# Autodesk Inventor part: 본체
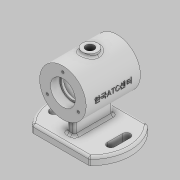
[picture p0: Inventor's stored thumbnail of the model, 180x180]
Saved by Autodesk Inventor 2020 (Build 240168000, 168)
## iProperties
Created: 2021-09
Part Number: 본체
Material: 일반
Document SubType Name: Modeling
Designer: Administrator
Density: 1 g/cm^3
Appearance: 기본값
Mass: 173.412 g
Surface Area: 488.146 cm^2
Volume: 173.412 cm^3
Author: Administrator
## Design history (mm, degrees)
sketch "스케치1"
  geometry: C1 r 30 at (0, 62); 1 further point
  constraints: 1 centre point
  dimensions: "d0" = 60 diameter of C1; "d1" = 62 distance of point (0, 0) C1.centre
extrude "돌출1" new body sketch "스케치1" stored distance "d2" = 70; taper "d3" = 0 deg
sketch "스케치2"
  geometry: C1 r 52.5 at (0, 0); 1 further point
  constraints: 1 centre point, 1 coincident
  dimensions: "d4" = 105 diameter of C1
extrude "돌출2" join sketch "스케치2" distance "d5" = 10; taper "d6" = 0 deg
sketch "스케치4"
  geometry: L1 (-122.101, -120.622)-(97.742, -120.622); L2 (97.742, -120.622)-(97.742, -37.5); L3 (97.742, -37.5)-(-122.101, -37.5); L4 (-122.101, -37.5)-(-122.101, -120.622); L5 (-52.5, 0)-(52.5, 0); A1 r 52.5 centre (0, 0) between (-52.5, 0) and (52.5, 0) reference; 2 further points
  constraints: 10 end point, 2 horizontal, 2 parallel, 2 point on circle, 1 coincident, 1 midpoint, 1 perpendicular
  dimensions: "d8" = 37.5 distance between parallel lines of L3 L5
extrude "돌출3" cut sketch "스케치4" extent not by distance; stored distance "d9" = 0; taper "d10" = 0 deg
sketch "스케치3"
  geometry: L1 (35.4, 25)-(4, 25); L2 (4, 25)-(4, -25); L3 (4, -25)-(35.4, -25); L4 (35.4, -25)-(35.4, 25); L5 (0, 0)-(92, 0); L6 (92, -35)-(92, 35) reference
  constraints: 10 end point, 2 parallel, 1 horizontal, 1 midpoint, 1 perpendicular, 1 other
  dimensions: "d7" = 50 distance of L3.end L1.start
extrude "돌출4" join sketch "스케치3" stored distance "d11" = 10; taper "d12" = 0 deg
sketch "스케치5"
  geometry: L1 (92, 35)-(32, 35) reference; L2 (62, 35)-(62, -35); L3 (32, -35)-(92, -35) reference; L4 (62, 35)-(78, 35); L5 (78, 35)-(78, 23); L6 (78, 23)-(76, 23); L7 (76, 23)-(76, 20); L8 (76, 20)-(87, 20); L9 (87, 20)-(87, -20); L10 (87, -20)-(76, -20); L11 (76, -20)-(76, -23); L12 (76, -23)-(78, -23); L13 (78, -23)-(78, -35); L14 (78, -35)-(62, -35); 1 further point
  constraints: 24 end point, 7 perpendicular, 2 midpoint, 2 point on line, 1 collinear, 1 horizontal, 1 vertical
  dimensions: "d13" = 28 diameter of L7 L2; "d14" = 28 diameter of L11 L2 (= d13); "d15" = 32 diameter of L5 L2; "d16" = 32 diameter of L13 L2 (= d15); "d17" = 50 diameter of L9 L2; "d18" = 12 distance of L4.end L5.end; "d19" = 12 distance of L12.end L13.end (= d18); "d20" = 40 distance of L8.end L9.end; "d21" = 3 distance of L6.end L7.end
revolve "회전1" sketch "스케치5" stored, may be unused: angle "d22" = 90 deg
sketch "스케치6"
  geometry: C1 r 30 at (0, 0) reference; 2 further points
  constraints: 1 vertical alignment
  dimensions: "d23" = 23 distance of C1.centre point (0, 23)
hole "구멍1" sketch "스케치6" at (0, 23) diameter "d24" = 3.242; stored, may be unused: countersink angle "d28" = 90 deg, drill point angle "d30" = 118 deg; dims "d25" = 8, "d26" = 4, "d27" = 2, "d29" = 10
node "작업 평면2"
sketch "스케치7"
  geometry: C1 r 10 at (0, 0); 1 further point
  constraints: 1 centre point, 1 coincident
  dimensions: "d36" = 20 diameter of C1
extrude "돌출5" join sketch "스케치7" stored distance "d37" = 10; taper "d38" = 0 deg
sketch "스케치8"
  geometry: C1 r 10 at (0, 0) reference; 2 further points
  constraints: 1 coincident
hole "구멍2" sketch "스케치8" at (0, 0) diameter "d39" = 10.917; stored, may be unused: countersink angle "d43" = 90 deg, drill point angle "d45" = 0 deg; dims "d40" = 24, "d41" = 4, "d42" = 2, "d44" = 29.1
sketch "스케치9"
  geometry: L1 (-36.742, 37.5)-(36.742, 37.5) reference; L2 (36.742, -37.5)-(-36.742, -37.5) reference; L3 (-37, -10)-(-37, 10); L4 (-32, -10)-(-32, 10); L5 (-42, 10)-(-42, -10); A1 r 52.5 centre (0, 0) between (36.742, -37.5) and (36.742, 37.5) reference; A2 r 52.5 centre (0, 0) between (-36.742, 37.5) and (-36.742, -37.5) reference; A3 r 5 centre (-37, -10) between (-42, -10) and (-32, -10); A4 r 5 centre (-37, 10) between (-32, 10) and (-42, 10); 2 further points
  constraints: 8 end point, 4 point on circle, 4 tangent, 2 centre point, 1 horizontal alignment, 1 midpoint, 1 parallel, 1 vertical
  dimensions: "d47" = 20 distance of L3.end L3.start; "d48" = 5 radius of A4; "d60" = 37 distance of point (0, 0) point (-37, 0)
extrude "돌출6" cut sketch "스케치9" stored distance "d49" = 10; taper "d50" = 0 deg
node "작업 평면4"
sketch "스케치10"
  geometry: L1 (92, 35)-(32, 35) reference; L2 (92, -35)-(92, 35) reference; 2 further points
  constraints: 1 other
  dimensions: "d52" = 35 distance from line of L1 point (62, 0); "d53" = 30 distance from line of L2 point (62, 0)
feature "엠보싱1" sketch "스케치10" dims "d8" = 37.5, "d54" = 0.5, "d55" = 0
fillet "모깎기1" dims "d56" = 3
fillet "모깎기2" dims "d57" = 3
fillet "모깎기3" dims "d58" = 3, "d59" = 0.3
node "솔리드1"
mirror "미러1"
pattern_circular "원형 패턴1" dims angle "d32" = 360 deg
mirror "미러2"
mirror "미러3"
node "투영된 루프1"
feature "A9D066F2-1C7D-4E18-AEED-F7BC21143FA4" dims "d24" = 3.242, "d25" = 8, "d26" = 4, "d27" = 2, "d28" = 90 deg, "d29" = 10, "d30" = 118 deg
other parameters: "d35" = 95, "d51" = 68
